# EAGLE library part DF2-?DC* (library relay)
HIGHLY SENSITIVE DIP MINIATURE RELAY NAiS Single side stable / 1 coil latching Source: http://www.mew-europe.com/.. en_ds_61002_0000.pdf
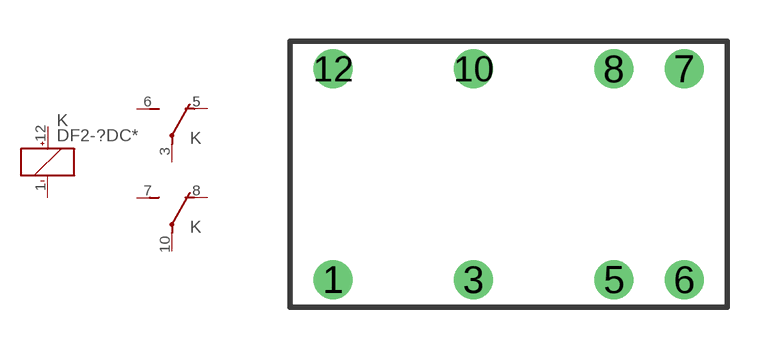
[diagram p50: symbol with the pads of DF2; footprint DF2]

Designator prefix K; gates 1=K+- 2=U 3=U

## DF2-DC1.5V (OC_FARNELL: unknown; OC_NEWARK: unknown), DF2-DC3V (OC_FARNELL: unknown; OC_NEWARK: unknown), DF2-DC5V (OC_FARNELL: unknown; OC_NEWARK: unknown), DF2-DC6V (OC_FARNELL: unknown; OC_NEWARK: unknown), DF2-DC9V (OC_FARNELL: unknown; OC_NEWARK: unknown), DF2-DC12V (OC_FARNELL: unknown; OC_NEWARK: unknown), DF2-DC24V (OC_FARNELL: unknown; OC_NEWARK: unknown)  [DF2]
1  1:-  pas
3  2:P  pas
5  2:O  pas
6  2:S  pas
7  3:S  pas
8  3:O  pas
10  3:P  pas
12  1:+  pas

## DF2-L-DC1.5V (OC_FARNELL: unknown; OC_NEWARK: unknown), DF2-L-DC3V (OC_FARNELL: unknown; OC_NEWARK: unknown), DF2-L-DC5V (OC_FARNELL: unknown; OC_NEWARK: unknown), DF2-L-DC6V (OC_FARNELL: unknown; OC_NEWARK: unknown), DF2-L-DC9V (OC_FARNELL: unknown; OC_NEWARK: unknown), DF2-L-DC12V (OC_FARNELL: unknown; OC_NEWARK: unknown), DF2-L-DC24V (OC_FARNELL: unknown; OC_NEWARK: unknown)  [DF2]
Pads as for DF2

## Footprint DF2 (pad centres in mm)
HIGHLY SENSITIVE DIP MINIATURE RELAY Source: http://www.mew-europe.com/.. en_ds_61002_0000.pdf
drill 0.9 round: 1 -6.35,-3.81; 3 -1.27,-3.81; 5 3.81,-3.81; 6 6.35,-3.81; 7 6.35,3.81; 8 3.81,3.81; 10 -1.27,3.81; 12 -6.35,3.81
